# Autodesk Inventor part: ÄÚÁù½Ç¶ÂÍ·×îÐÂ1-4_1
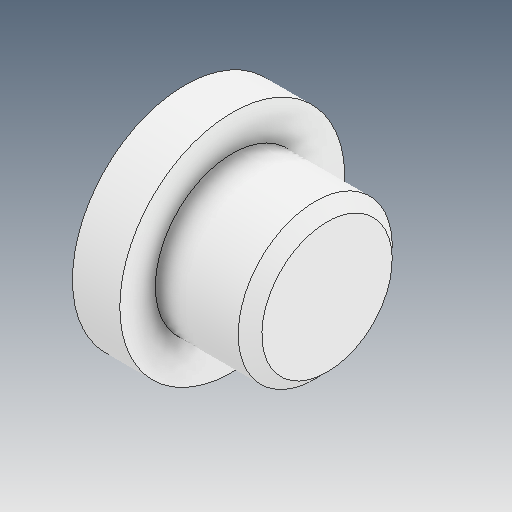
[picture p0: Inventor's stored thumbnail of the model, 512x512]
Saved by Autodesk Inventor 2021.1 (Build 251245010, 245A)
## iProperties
Created: 2021-05
Part Number: ÄÚÁù½Ç¶ÂÍ·×îÐÂ1-4_1
Material: Ogólny
Document SubType Name: Modeling
Designer: user
Density: 1 g/cm^3
Appearance: Domyślna
Author: user
Revision Number: ÈÎºÎ
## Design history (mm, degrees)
feature "ÊäÈë1"
node "Bryła1"
